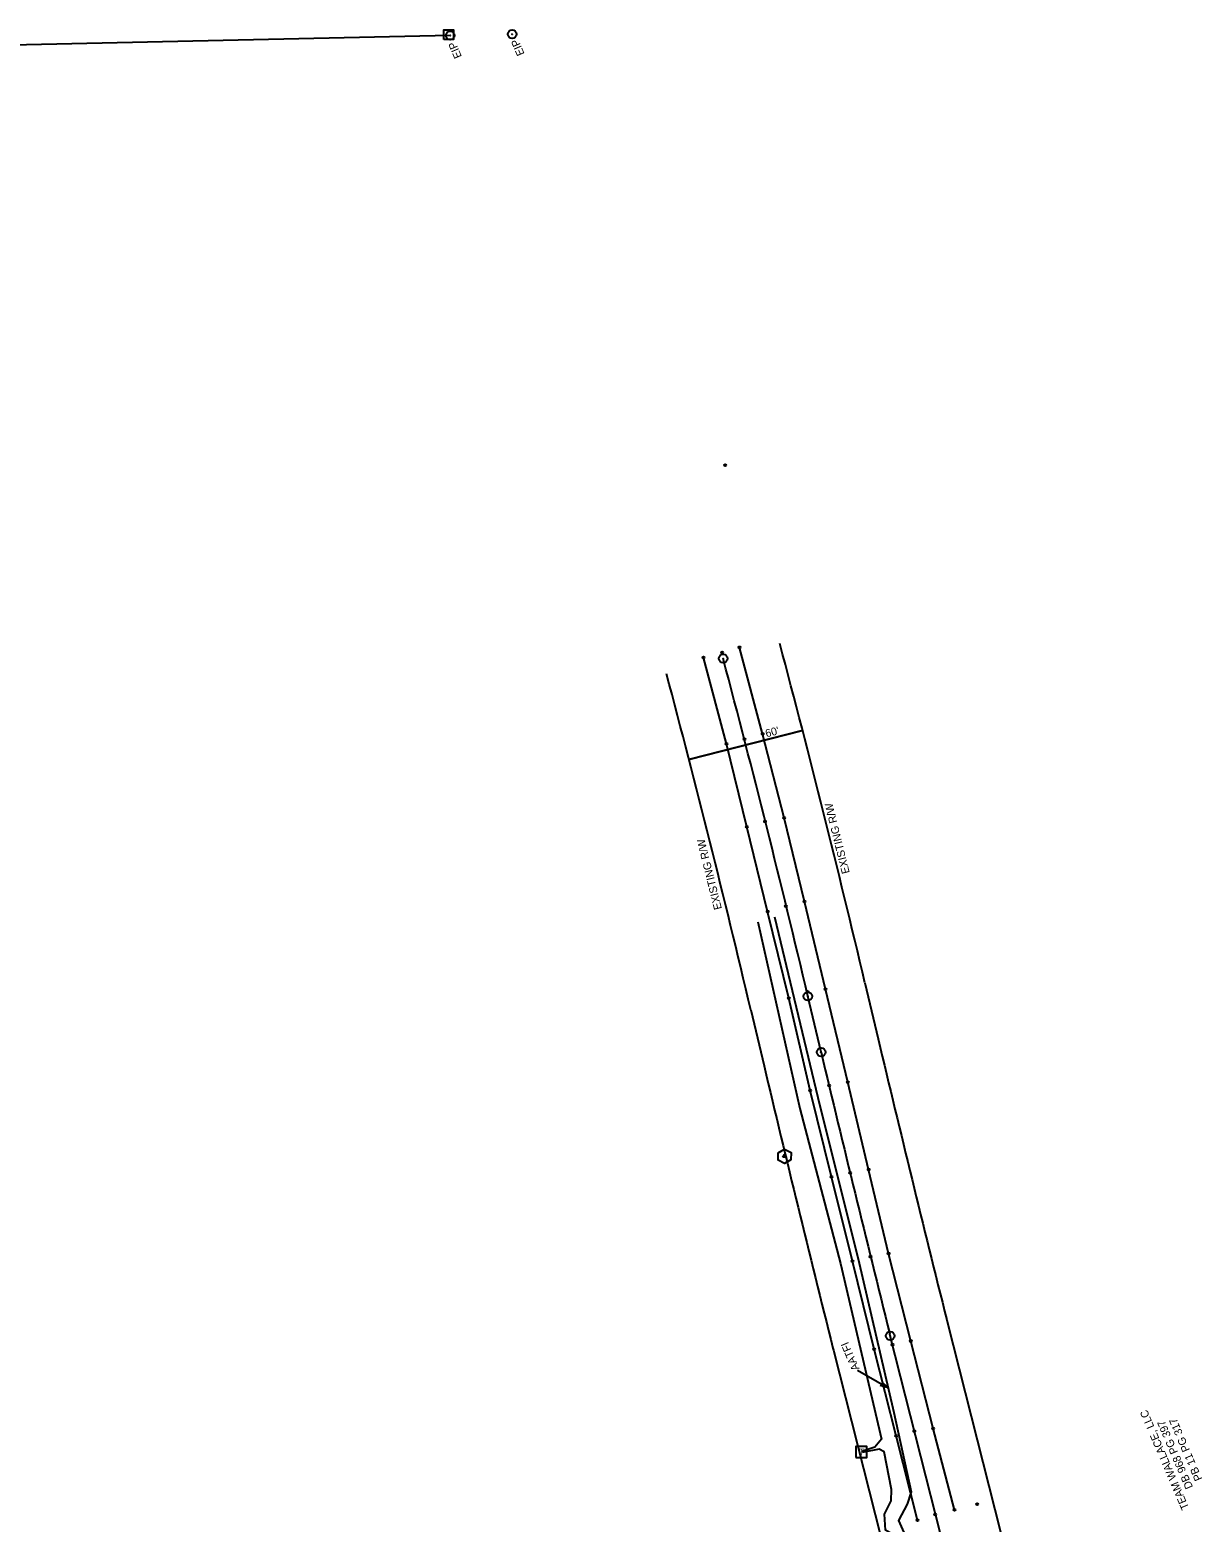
# Model space of a CAD drawing. Extents: x 1550153 to 1552579, y 809637 to 812160.
# Drawn here: x 1551164 to 1551764, y 811397 to 812160 of the extents above; entities that cross this region are included whole.
import ezdxf

# ---------------------------------------------------------------- set-up
doc = ezdxf.new("R2010")
doc.units = 0
for name, color, linetype in [('CTL Primary Horizontal and Vertical CELL', 7, 'Continuous'), ('Default', 7, 'Continuous'), ('E_NCDOT_Horizontal_Alignment', 7, 'Continuous'), ('E_NCDOT_Horizontal_Alignment_Curve', 7, 'Continuous'), ('E_NCDOT_Horizontal_Alignment_Tick_Label', 7, 'Continuous'), ('Exist Property Iron Pin CELL', 7, 'Continuous'), ('Exist Property Iron Pin Text', 7, 'Continuous'), ('Exist Property Line', 7, 'Continuous'), ('Exist Property Monument CELL', 7, 'Continuous'), ('Exist Property Text', 7, 'Continuous'), ('Exist Right of Way Line', 7, 'Continuous'), ('Exist Right of Way Line Leader', 7, 'Continuous'), ('Exist Right of Way Line Text', 7, 'Continuous'), ('Exist Roads EOP', 7, 'Continuous'), ('Exist Survey Control Group', 7, 'Continuous'), ('Exist Utilities Telephone Pedestal CELL', 7, 'Continuous'), ('Exist Utilities Telephone Text', 7, 'Continuous'), ('Exist Utilities Telephone UG Cable SUE LOS B', 7, 'Continuous')]:
    doc.layers.add(name, color=color, linetype=linetype)

# ---------------------------------------------------------------- blocks, each defined once
blk = doc.blocks.new('SurveyPointCell')
at = {"layer": 'Default'}
for p, q in [((-0.5, 0), (0.5, 0)), ((0, -0.5), (0, 0.5))]:
    blk.add_line(p, q, dxfattribs=at)
blk.add_circle((0, 0), 0.5, dxfattribs=at)
blk = doc.blocks.new('SurveyControlPointCell')
at = {"layer": 'Default'}
for p, q in [((-0.87, -0.5), (0, 1)), ((0, 1), (0.87, -0.5)), ((0.87, -0.5), (-0.87, -0.5))]:
    blk.add_line(p, q, dxfattribs=at)
blk.add_circle((0, 0), 0.5, dxfattribs=at)

msp = doc.modelspace()

# ---------------------------------------------------------------- linework, layer by layer
at = {"layer": 'CTL Primary Horizontal and Vertical CELL'}
msp.add_line((1551550.43, 811583.92), (1551550.43, 811583.92), dxfattribs=at)
msp.add_line((1551550.43, 811583.92), (1551550.43, 811583.92), dxfattribs=at)
msp.add_line((1551550.43, 811583.92), (1551550.43, 811583.92), dxfattribs=at)
msp.add_lwpolyline([(1551547.2, 811585.79), (1551550.45, 811587.6), (1551553.7, 811585.81), (1551553.65, 811582.09), (1551550.4, 811580.2), (1551547.2, 811582.01)], close=True, dxfattribs=at)
msp.add_lwpolyline([(1551547.2, 811585.79), (1551550.45, 811587.6), (1551553.7, 811585.81), (1551553.65, 811582.09), (1551550.4, 811580.2), (1551547.2, 811582.01)], close=True, dxfattribs=at)
msp.add_lwpolyline([(1551547.2, 811585.79), (1551550.45, 811587.6), (1551553.7, 811585.81), (1551553.65, 811582.09), (1551550.4, 811580.2), (1551547.2, 811582.01)], close=True, dxfattribs=at)
at = {"layer": 'Default'}
msp.add_line((1551550.43, 811583.92), (1551550.43, 811583.92), dxfattribs=at)
msp.add_arc((1564896.1, 814812.14), 13700, 193.400037, 194.02081, dxfattribs=at)
msp.add_arc((1564896.1, 814812.14), 13700, 193.400037, 194.02081, dxfattribs=at)
msp.add_arc((1564896.1, 814812.14), 13700, 193.400037, 194.02081, dxfattribs=at)
at = {"layer": 'E_NCDOT_Horizontal_Alignment'}
for p, q in [((1551569.07, 811637.18), (1551562.31, 811665.8)), ((1551604.47, 811492.11), (1551604.25, 811492.98)), ((1551638.16, 811359.58), (1551604.47, 811492.11))]:
    msp.add_line(p, q, dxfattribs=at)
for centre, radius in [((1551518.96, 811838.6), 2.2), ((1551518.96, 811838.6), 0.0707), ((1551562.31, 811665.8), 2.2), ((1551562.31, 811665.8), 0.0707), ((1551569.07, 811637.18), 2.2), ((1551569.07, 811637.18), 0.0707), ((1551604.47, 811492.11), 2.2), ((1551604.47, 811492.11), 0.0707)]:
    msp.add_circle(centre, radius, dxfattribs=at)
at = {"layer": 'E_NCDOT_Horizontal_Alignment_Curve'}
for centre, radius, start, end in [((1545721.6, 810292.47), 6000, 13.23164, 14.932933), ((1545721.6, 810292.47), 6000, 13.23164, 14.932933), ((1564896.1, 814812.14), 13700, 193.400037, 194.02081), ((1564896.1, 814812.14), 13700, 193.400037, 194.02081)]:
    msp.add_arc(centre, radius, start, end, dxfattribs=at)
at = {"layer": 'E_NCDOT_Horizontal_Alignment_Tick_Label'}
msp.add_arc((1564896.1, 814812.14), 13700, 193.400037, 194.02081, dxfattribs=at)
at = {"layer": 'Exist Property Iron Pin CELL'}
for centre, radius in [((1551379.37, 812157.44), 2.2), ((1551379.37, 812157.44), 2.2), ((1551379.37, 812157.44), 2.2), ((1551379.37, 812157.44), 0.0707), ((1551379.37, 812157.44), 0.0707), ((1551379.37, 812157.44), 0.0707), ((1551410.98, 812158.1), 2.2), ((1551410.98, 812158.1), 2.2), ((1551410.98, 812158.1), 0.0707), ((1551410.98, 812158.1), 0.0707)]:
    msp.add_circle(centre, radius, dxfattribs=at)
at = {"layer": 'Exist Property Line'}
msp.add_line((1551379.37, 812157.44), (1550155.57, 812130.91), dxfattribs=at)
at = {"layer": 'Exist Property Monument CELL'}
msp.add_line((1551378.57, 812157.84), (1551378.57, 812157.84), dxfattribs=at)
msp.add_line((1551378.57, 812157.84), (1551378.57, 812157.84), dxfattribs=at)
msp.add_line((1551378.57, 812157.84), (1551378.57, 812157.84), dxfattribs=at)
msp.add_lwpolyline([(1551376.08, 812155.34), (1551376.08, 812160.33), (1551381.07, 812160.33), (1551381.07, 812155.34), (1551376.08, 812155.34)], dxfattribs=at)
msp.add_lwpolyline([(1551376.08, 812155.34), (1551376.08, 812160.33), (1551381.07, 812160.33), (1551381.07, 812155.34), (1551376.08, 812155.34)], dxfattribs=at)
msp.add_lwpolyline([(1551376.08, 812155.34), (1551376.08, 812160.33), (1551381.07, 812160.33), (1551381.07, 812155.34), (1551376.08, 812155.34)], dxfattribs=at)
at = {"layer": 'Exist Right of Way Line'}
msp.add_line((1551591.51, 811672.69), (1551598.26, 811644.11), dxfattribs=at)
for points in [[(1551533.11, 811658.94), (1551533.11, 811658.92), (1551539.88, 811630.26), (1551539.89, 811630.23)], [(1551633.36, 811500.25), (1551633.56, 811499.43), (1551667.25, 811366.92), (1551679.36, 811318.56)], [(1551575.15, 811485.71), (1551575.38, 811484.78), (1551609.07, 811352.24), (1551621.15, 811303.99)]]:
    msp.add_lwpolyline(points, dxfattribs=at)
for centre, radius, start, end in [((1545721.6, 810292.47), 6030, 13.231792, 14.932933), ((1545721.6, 810292.47), 5970, 13.23164, 14.932933), ((1564896.1, 814812.14), 13670, 193.400155, 194.02081), ((1564896.1, 814812.14), 13730, 193.400037, 194.02081)]:
    msp.add_arc(centre, radius, start, end, dxfattribs=at)
at = {"layer": 'Exist Right of Way Line Leader'}
for p, q in [((1551501.5, 811786.99), (1551559.64, 811801.82)), ((1551559.64, 811801.82), (1551501.5, 811786.99))]:
    msp.add_line(p, q, dxfattribs=at)
at = {"layer": 'Exist Roads EOP'}
for points in [[(1551637.28, 811403.02), (1551626.4, 811444.66), (1551615.07, 811489.43), (1551603.65, 811534.15), (1551593.42, 811577.24), (1551582.77, 811621.83), (1551571.37, 811669.46), (1551560.56, 811714.33), (1551550.2, 811757.15), (1551539.19, 811800.15), (1551527.36, 811844.37)], [(1551618.39, 811397.72), (1551607.45, 811440.85), (1551596.26, 811485.28), (1551585.1, 811530.33), (1551574.36, 811573.51), (1551563.53, 811617.58), (1551552.6, 811664.91), (1551541.75, 811709.22), (1551531.12, 811752.56), (1551520.63, 811794.97), (1551508.88, 811839.17)]]:
    msp.add_lwpolyline(points, dxfattribs=at)
at = {"layer": 'Exist Survey Control Group'}
msp.add_line((1551550.43, 811583.92), (1551550.43, 811583.92), dxfattribs=at)
msp.add_lwpolyline([(1551549.57, 811583.42), (1551550.43, 811584.92), (1551551.3, 811583.42)], close=True, dxfattribs=at)
msp.add_circle((1551550.43, 811583.92), 0.5, dxfattribs=at)
at = {"layer": 'Exist Utilities Telephone Pedestal CELL'}
msp.add_line((1551589.62, 811432.64), (1551589.62, 811432.64), dxfattribs=at)
msp.add_lwpolyline([(1551586.89, 811429.81), (1551592.49, 811429.81), (1551592.49, 811435.41), (1551586.89, 811435.41), (1551586.89, 811429.81)], dxfattribs=at)
at = {"layer": 'Exist Utilities Telephone Text'}
msp.add_lwpolyline([(1551587.75, 811474.53), (1551603.34, 811465.52), (1551600.36, 811468.4), (1551603.34, 811465.52), (1551599.36, 811466.66)], dxfattribs=at)
at = {"layer": 'Exist Utilities Telephone UG Cable SUE LOS B'}
for points in [[(1551536.68, 811703.91), (1551558.25, 811608.46), (1551578.97, 811529.07), (1551600, 811439.28), (1551596.52, 811435.16), (1551590.01, 811432.95)], [(1551545.22, 811706.56), (1551568.37, 811609.79), (1551588, 811531.44), (1551606.27, 811452.93), (1551615.14, 811412.25), (1551613.21, 811406), (1551608.7, 811397.66), (1551611.45, 811391.52), (1551618.85, 811384.02), (1551621.83, 811380.6), (1551621.74, 811378.31), (1551618.28, 811376.25), (1551614.11, 811374.91), (1551603.55, 811373.65)], [(1551603.05, 811374.46), (1551606.52, 811376.87), (1551611, 811379.06), (1551611.78, 811380.7), (1551609.42, 811387.99), (1551605.7, 811390.64), (1551602.03, 811392.68), (1551601.58, 811400.81), (1551604.98, 811407.57), (1551605.14, 811413.37), (1551601.39, 811432.74), (1551598.88, 811434.08), (1551590.03, 811432.32)]]:
    msp.add_lwpolyline(points, dxfattribs=at)

# ---------------------------------------------------------------- block references
at = {"layer": 'Default'}
for name, p in [('SurveyPointCell', (1551520.06, 811937.59)), ('SurveyPointCell', (1551520.06, 811937.59)), ('SurveyPointCell', (1551518.46, 811841.68)), ('SurveyPointCell', (1551518.46, 811841.68)), ('SurveyPointCell', (1551527.36, 811844.37)), ('SurveyPointCell', (1551527.36, 811844.37)), ('SurveyPointCell', (1551508.88, 811839.17)), ('SurveyPointCell', (1551508.88, 811839.17)), ('SurveyPointCell', (1551520.63, 811794.97)), ('SurveyPointCell', (1551520.63, 811794.97)), ('SurveyPointCell', (1551529.96, 811797.42)), ('SurveyPointCell', (1551529.96, 811797.42)), ('SurveyPointCell', (1551539.19, 811800.15)), ('SurveyPointCell', (1551539.19, 811800.15)), ('SurveyPointCell', (1551550.2, 811757.15)), ('SurveyPointCell', (1551550.2, 811757.15)), ('SurveyPointCell', (1551531.12, 811752.56)), ('SurveyPointCell', (1551531.12, 811752.56)), ('SurveyPointCell', (1551540.4, 811755.31)), ('SurveyPointCell', (1551540.4, 811755.31)), ('SurveyPointCell', (1551551.09, 811711.95)), ('SurveyPointCell', (1551551.09, 811711.95)), ('SurveyPointCell', (1551560.56, 811714.33)), ('SurveyPointCell', (1551560.56, 811714.33)), ('SurveyPointCell', (1551541.75, 811709.22)), ('SurveyPointCell', (1551541.75, 811709.22)), ('SurveyPointCell', (1551552.6, 811664.91)), ('SurveyPointCell', (1551552.6, 811664.91)), ('SurveyPointCell', (1551562.08, 811668.09)), ('SurveyPointCell', (1551562.08, 811668.09)), ('SurveyPointCell', (1551571.37, 811669.46)), ('SurveyPointCell', (1551571.37, 811669.46)), ('SurveyPointCell', (1551573.17, 811620.17)), ('SurveyPointCell', (1551573.17, 811620.17)), ('SurveyPointCell', (1551582.77, 811621.83)), ('SurveyPointCell', (1551582.77, 811621.83)), ('SurveyPointCell', (1551563.53, 811617.58)), ('SurveyPointCell', (1551563.53, 811617.58)), ('SurveyControlPointCell', (1551550.43, 811583.92)), ('SurveyControlPointCell', (1551550.43, 811583.92)), ('SurveyPointCell', (1551574.36, 811573.51)), ('SurveyPointCell', (1551574.36, 811573.51)), ('SurveyPointCell', (1551583.96, 811575.43)), ('SurveyPointCell', (1551583.96, 811575.43)), ('SurveyPointCell', (1551593.42, 811577.24)), ('SurveyPointCell', (1551593.42, 811577.24)), ('SurveyPointCell', (1551603.65, 811534.15)), ('SurveyPointCell', (1551603.65, 811534.15)), ('SurveyPointCell', (1551585.1, 811530.33)), ('SurveyPointCell', (1551585.1, 811530.33)), ('SurveyPointCell', (1551594.4, 811532.6)), ('SurveyPointCell', (1551594.4, 811532.6)), ('SurveyPointCell', (1551615.07, 811489.43)), ('SurveyPointCell', (1551615.07, 811489.43)), ('SurveyPointCell', (1551596.26, 811485.28)), ('SurveyPointCell', (1551596.26, 811485.28)), ('SurveyPointCell', (1551605.57, 811487.55)), ('SurveyPointCell', (1551605.57, 811487.55)), ('SurveyPointCell', (1551616.79, 811443.3)), ('SurveyPointCell', (1551616.79, 811443.3)), ('SurveyPointCell', (1551626.4, 811444.66)), ('SurveyPointCell', (1551626.4, 811444.66)), ('SurveyPointCell', (1551607.45, 811440.85)), ('SurveyPointCell', (1551607.45, 811440.85)), ('SurveyPointCell', (1551648.89, 811405.97)), ('SurveyPointCell', (1551648.89, 811405.97)), ('SurveyPointCell', (1551618.39, 811397.72)), ('SurveyPointCell', (1551618.39, 811397.72)), ('SurveyPointCell', (1551627.43, 811400.69)), ('SurveyPointCell', (1551627.43, 811400.69)), ('SurveyPointCell', (1551637.28, 811403.02)), ('SurveyPointCell', (1551637.28, 811403.02))]:
    msp.add_blockref(name, p, dxfattribs=at)

# ---------------------------------------------------------------- texts
at = {"layer": 'Exist Property Iron Pin Text'}
for p in [(1551385.35, 812146.7), (1551417.44, 812148.06)]:
    msp.add_text('EIP', height=4.02, rotation=113.17361, dxfattribs=at).set_placement(p)
at = {"layer": 'Exist Property Text'}
for s, p in [('TEAM WALLACE, LLC', (1551757.42, 811404.1)), ('DB 968 PG 397', (1551759.44, 811414.71)), ('PB 11 PG 317', (1551764.22, 811418.85))]:
    msp.add_text(s, height=4.02, rotation=113.17361, dxfattribs=at).set_placement(p)
at = {"layer": 'Exist Right of Way Line Text'}
for s, rotation, p in [("60'", 14.31171, (1551541.12, 811798.28)), ('EXISTING R/W', 103.95863, (1551583.76, 811729.07)), ('EXISTING R/W', 103.95863, (1551518.35, 811710.67))]:
    msp.add_text(s, height=4.02, rotation=rotation, dxfattribs=at).set_placement(p)
at = {"layer": 'Exist Utilities Telephone Pedestal CELL'}
msp.add_text('T', height=3.42, dxfattribs=at).set_placement((1551588.49, 811430.93))
at = {"layer": 'Exist Utilities Telephone Text'}
msp.add_text('AATFI', height=4.02, rotation=113.1736, dxfattribs=at).set_placement((1551588.77, 811475.33))

doc.saveas('drawing.dxf')
